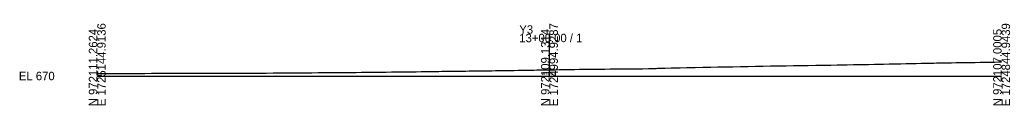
# Model space of a CAD drawing. Extents: x -26 to 303, y -10 to 3017.
# Drawn here: x -25.7 to 302.8, y 2990.3 to 3017.3 of the extents above; entities that cross this region are included whole.
import ezdxf

# ---------------------------------------------------------------- set-up
doc = ezdxf.new("R2010")
doc.units = 0
for name, color, linetype in [('Default', 7, 'Continuous'), ('Exist Other Culture Gate Leader', 7, 'Continuous'), ('Exist Roads Soil Text', 7, 'Continuous'), ('Exist Structure Minor Culvert Topo Terminator', 7, 'Continuous')]:
    doc.layers.add(name, color=color, linetype=linetype)

msp = doc.modelspace()

# ---------------------------------------------------------------- linework, layer by layer
at = {"layer": 'Exist Other Culture Gate Leader'}
msp.add_lwpolyline([(0, 3000.85), (0.82, 3000.85), (2.77, 3000.85), (3.33, 3000.85), (3.86, 3000.85), (5.82, 3000.86), (6.33, 3000.86), (8.33, 3000.86), (8.83, 3000.86), (10.82, 3000.87), (12.88, 3000.88), (13.32, 3000.88), (15.43, 3000.88), (15.83, 3000.88), (17.99, 3000.89), (18.33, 3000.89), (18.65, 3000.89), (20.82, 3000.89), (21.15, 3000.89), (23.32, 3000.89), (23.63, 3000.89), (25.82, 3000.9), (28.33, 3000.92), (30.99, 3000.93), (33.49, 3000.94), (35.82, 3000.95), (38.32, 3000.96), (40.87, 3000.96), (43.32, 3000.96), (44.97, 3000.96), (45.82, 3000.97), (48.33, 3000.97), (50.82, 3000.98), (53.32, 3000.99), (56, 3000.99), (58.32, 3001), (60.82, 3001.02), (63.59, 3001.03), (65.83, 3001.05), (66.15, 3001.05), (68.33, 3001.07), (70.45, 3001.08), (70.82, 3001.08), (71.2, 3001.09), (73.33, 3001.11), (75.38, 3001.12), (75.82, 3001.13), (76.27, 3001.13), (78.34, 3001.15), (78.85, 3001.15), (80.83, 3001.16), (82.78, 3001.18), (83.33, 3001.18), (83.9, 3001.19), (85.83, 3001.21), (87.7, 3001.24), (88.33, 3001.24), (90.18, 3001.26), (90.83, 3001.26), (92.64, 3001.28), (93.32, 3001.29), (94.03, 3001.3), (95.83, 3001.32), (97.57, 3001.34), (98.33, 3001.35), (100.04, 3001.37), (100.82, 3001.38), (101.65, 3001.39), (103.34, 3001.41), (104.96, 3001.43), (105.82, 3001.44), (107.44, 3001.46), (108.34, 3001.48), (109.9, 3001.5), (110.82, 3001.51), (111.78, 3001.52), (113.34, 3001.54), (114.33, 3001.56), (115.82, 3001.57), (116.87, 3001.58), (118.34, 3001.6), (119.75, 3001.62), (120.82, 3001.64), (122.23, 3001.66), (123.35, 3001.67), (124.68, 3001.69), (125.83, 3001.7), (127.15, 3001.72), (128.33, 3001.73), (129.55, 3001.75), (130.84, 3001.77), (132.07, 3001.78), (133.32, 3001.8), (134.63, 3001.82), (135.84, 3001.84), (137.02, 3001.86), (138.33, 3001.88), (139.7, 3001.9), (140.84, 3001.92), (141.95, 3001.93), (143.33, 3001.96), (144.78, 3001.98), (145.85, 3002), (147.3, 3002.03), (148.33, 3002.05), (150, 3002.07), (150.84, 3002.09), (151.8, 3002.1), (153.33, 3002.13), (154.91, 3002.15), (155.84, 3002.16), (156.73, 3002.18), (158.34, 3002.2), (159.98, 3002.22), (160.84, 3002.23), (161.66, 3002.23), (163.33, 3002.25), (164.13, 3002.27), (165.85, 3002.29), (167.6, 3002.31), (168.33, 3002.32), (170.14, 3002.33), (170.85, 3002.34), (171.53, 3002.35), (173.33, 3002.37), (175.21, 3002.38), (175.85, 3002.38), (177.74, 3002.4), (178.33, 3002.41), (178.91, 3002.41), (180.84, 3002.43), (182.82, 3002.48), (183.34, 3002.49), (185.35, 3002.54), (185.84, 3002.55), (187.89, 3002.6), (188.34, 3002.61), (190.42, 3002.67), (190.83, 3002.69), (191.24, 3002.7), (193.35, 3002.74), (195.49, 3002.78), (195.83, 3002.79), (198.04, 3002.83), (198.35, 3002.84), (200.85, 3002.89), (203.55, 3002.94), (205.85, 3002.99), (208.34, 3003.04), (210.83, 3003.09), (213.35, 3003.14), (215.87, 3003.18), (218.35, 3003.23), (218.99, 3003.24), (220.87, 3003.28), (223.33, 3003.32), (225.96, 3003.36), (228.48, 3003.4), (231.01, 3003.44), (233.57, 3003.47), (235.86, 3003.51), (238.33, 3003.54), (238.63, 3003.55), (240.84, 3003.59), (241.17, 3003.59), (243.36, 3003.63), (245.45, 3003.66), (245.83, 3003.67), (246.23, 3003.67), (248.34, 3003.71), (248.78, 3003.72), (250.86, 3003.76), (251.33, 3003.77), (253.35, 3003.81), (255.3, 3003.85), (255.83, 3003.86), (257.78, 3003.9), (258.34, 3003.91), (258.93, 3003.92), (260.86, 3003.97), (262.7, 3004), (263.34, 3004.02), (265.16, 3004.05), (265.83, 3004.07), (266.53, 3004.08), (268.34, 3004.12), (269.08, 3004.13), (270.85, 3004.17), (271.62, 3004.19), (273.36, 3004.22), (274.17, 3004.24), (275.87, 3004.27), (277.5, 3004.3), (278.35, 3004.32), (279.96, 3004.35), (280.84, 3004.36), (282.4, 3004.39), (283.32, 3004.41), (284.86, 3004.43), (285.83, 3004.45), (286.82, 3004.46), (288.33, 3004.49), (289.36, 3004.5), (290.84, 3004.53), (291.24, 3004.53), (292.84, 3004.56), (293.35, 3004.57), (293.8, 3004.57), (295.27, 3004.6), (295.86, 3004.6), (296.35, 3004.61), (297.68, 3004.63), (298.91, 3004.65), (300, 3004.67)], dxfattribs=at)
at = {"layer": 'Exist Structure Minor Culvert Topo Terminator'}
for p, q in [((150, 3000), (150, 3014)), ((0, 3000), (150, 3000)), ((150, 3000), (300, 3000))]:
    msp.add_line(p, q, dxfattribs=at)

# ---------------------------------------------------------------- texts
at = {"layer": 'Default'}
msp.add_text('-', height=0.0001, dxfattribs=at).set_placement((0, 3000))
at = {"layer": 'Exist Roads Soil Text'}
msp.add_text('672.07', height=1, dxfattribs=at).set_placement((147.81, 3000.35))
at = {"layer": 'Exist Structure Minor Culvert Topo Terminator'}
for s, p in [('E 1725144.9136', (2.8, 2990)), ('E 1724994.9287', (152.8, 2990)), ('E 1724844.9439', (302.8, 2990)), ('N 972111.2624', (0, 2990)), ('N 972109.1314', (150, 2990)), ('N 972107.0005', (300, 2990))]:
    msp.add_text(s, height=2.8, rotation=90, dxfattribs=at).set_placement(p)
for s, p in [('Y3', (140, 3014)), ('13+00.00 / 1', (140, 3011.2)), ('EL 670', (-26, 2998.6))]:
    msp.add_text(s, height=2.8, dxfattribs=at).set_placement(p)

doc.saveas('drawing.dxf')
